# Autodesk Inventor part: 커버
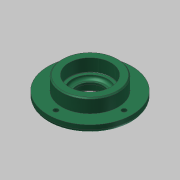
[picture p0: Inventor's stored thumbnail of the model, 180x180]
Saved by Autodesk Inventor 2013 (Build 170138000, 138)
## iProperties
Company: 한국ATC센터
Created: 2014-10
Part Number: 커버
Document SubType Name: Modeling
Designer: KYOUNG IL JANG
Density: 7.86 g/cm^3
Mass: 351.567 g
Surface Area: 161.165 cm^2
Volume: 44.7286 cm^3
Material: 알루미늄 6061
Author: KYOUNG IL JANG
Revision Number: 1
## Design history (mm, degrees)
sketch "스케치1"
  geometry: C1 r 40 at (0, 0); 1 further point
  constraints: 1 centre point, 1 coincident
  dimensions: "d0" = 80 diameter of C1
extrude "돌출1" new body sketch "스케치1" distance "d1" = 7; taper "d2" = 0 deg
sketch "스케치2"
  geometry: C1 r 27 at (0, 0); 1 further point
  constraints: 1 centre point, 1 coincident
  dimensions: "d3" = 54 diameter of C1
extrude "돌출2" join sketch "스케치2" distance "d4" = 13; taper "d5" = 0 deg
sketch "스케치3"
  geometry: C1 r 20 at (0, 0); 1 further point
  constraints: 1 centre point, 1 coincident
  dimensions: "d6" = 40 diameter of C1
extrude "돌출3" join sketch "스케치3" distance "d7" = 5; taper "d8" = 0 deg
hole "구멍1" diameter "d11" = 25; stored, may be unused: countersink angle "d15" = 90 deg, drill point angle "d17" = 118 deg; dims "d9" = 10, "d10" = 10, "d12" = 6, "d13" = 32, "d14" = 8.3, "d16" = 8
hole "구멍2" diameter "d20" = 34; stored, may be unused: countersink angle "d24" = 90 deg, drill point angle "d26" = 0 deg; dims "d18" = 10, "d19" = 10, "d21" = 6, "d22" = 40, "d23" = 12, "d25" = 3
fillet "모깎기2" dims "d34" = 3
fillet "모깎기1" dims "d27" = 0.3
chamfer "모따기1" distance "d28" = 1; stored, may be unused: second distance "d29" = 2, angle "d30" = 45 deg
chamfer "모따기2" distance "d31" = 1.2; stored, may be unused: second distance "d32" = 2, angle "d33" = 30 deg
sketch "스케치4" dims "d35" = 65
  geometry: 3 further points
  constraints: 2 horizontal alignment, 1 coincident, 2 other
hole "구멍3" sketch "스케치4" at (32.5, 0) diameter "d36" = 4.5; stored, may be unused: countersink angle "d40" = 90 deg, drill point angle "d42" = 118 deg; dims "d37" = 6, "d38" = 8, "d39" = 4.4, "d41" = 13
node "솔리드1"
pattern_circular "원형 패턴1" dims angle "d44" = 360 deg
